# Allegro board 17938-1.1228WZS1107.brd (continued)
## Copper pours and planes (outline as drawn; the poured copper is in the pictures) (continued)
3D3V_S5 on BOTTOM: 54.17,103.89 54.06,104 54.06,106.18 54.31,106.43 54.92,106.43 55.04,106.3 55.04,105.77 55.27,105.54 55.97,105.54 56.22,105.3 56.22,103.91 56.19,103.89
3D3V_S5 on BOTTOM: 146.84,143.84 146.61,144.07 146.61,144.81 146.89,145.09 147.5,145.09 148.01,145.59 148.97,145.59 149.13,145.44 149.13,143.84 ; 2 cut-outs
3D3V_S5 on BOTTOM: 165.43,108.76 165.05,109.15 165.05,109.58 165.18,109.7 165.43,109.7 165.51,109.78 165.51,111.53 165.36,111.69 162.28,111.69 162.23,111.74 162.23,114.66 162.28,114.71 166.58,114.71 167.06,114.23 167.06,108.92 166.91,108.76 ; 1 cut-out
3D3V_S5 on BOTTOM: 34.7,122.28 34.67,122.3 34.67,122.56 34.33,122.9 34.05,122.9 33.91,123.04 33.91,123.34 34.01,123.45 36.12,123.45 36.17,123.39 36.17,123.06 36.02,122.91 35.46,122.91 35.36,122.81 35.36,122.48 35.16,122.28
3D3V_S5 on BOTTOM: 62,119.38 59.64,121.74 59.57,121.74 58.3,123.01 57.58,123.01 56.39,124.21 56.39,125.88 56.29,125.99 56.29,126.39 56.47,126.57 59.41,126.57 59.46,126.62 59.46,127.23 59.49,127.26 60.18,127.26 60.4,127.03 60.4,125.45 60.84,125.02 62.97,125.02 63.58,125.63 63.58,128.07 63.21,128.44 62.47,128.44 62.32,128.59 62.32,128.66 62.28,128.7 60.12,128.7 60.07,128.65 59.52,128.65 59.44,128.73 59.44,129.41 59.01,129.85 59.01,130.58 59.19,130.76 63.76,130.76 64.6,129.92 68.33,129.92 69.04,129.21 69.04,120.27 68.15,119.38 ; 13 cut-outs
3D3V_S5 on L2SGND: 59.95,128.86 58.68,130.13 58.68,134.09 74.27,149.68 97.64,149.68 99.85,147.47 104.8,147.47 107.06,149.73 121.14,149.73 122.99,147.88 126.65,147.88 128.53,149.76 154.21,149.76 154.84,149.12 154.84,147.37 153.47,146 143.59,146 143.21,146.38 141.4,146.38 140.72,145.7 129.67,145.7 128.3,144.32 120.98,144.32 118.88,146.43 108.66,146.43 106.66,144.43 98.28,144.43 97.59,145.11 86.87,145.11 86.11,145.87 77.88,145.87 73.84,141.83 73.31,141.83 71.94,140.46 69.9,140.46 62.06,132.61 62.06,129.49 61.42,128.86
3D3V_S5 on L2SGND: 81.16,28.04 91.85,28.04 92.32,28.51 94,28.51 94.06,28.45 96.73,28.45 97.64,29.36 97.64,32.41 97.03,33.02 95.89,33.02 94.69,31.83 90.73,31.83 90.71,31.8 87.38,31.8 85.83,30.25 81.71,30.25 80.65,31.32 79.1,31.32 78.69,30.91 78.69,30.51
3D3V_S5 on L2SGND: 224.39,64.14 224.39,47.75 224.67,47.47 225.45,47.47 226.01,48.03 226.01,65.94 223.09,68.86 219.66,68.86 219,68.2 218.42,68.2 218.04,67.82 218.04,66.96 218.14,66.85 222.2,66.85 222.76,66.3 222.76,65.76
3D3V_S5 on L2SGND: 50.74,74.23 49.41,72.9 47.63,72.9 47.3,73.23 47.3,73.66 46.97,73.99 46.64,73.99 42.42,69.78 42.09,69.78 41.53,69.22 41.53,68.76 41.79,68.51 42.93,68.51 43.56,69.14 45.39,69.14 45.75,68.78 45.75,68.15 46.08,67.82 46.08,61.49 35.62,51.03 35.62,48 35.23,47.61 35.23,44.26 37.07,42.42 37.9,41.58 51.44,41.58 53.47,39.55 57.71,39.55 57.81,39.65 58.47,39.65 59.52,38.61 62.49,38.61 64.04,37.06 64.47,37.06 65.23,36.3 74.58,36.3 74.91,36.63 75.64,36.63 76.2,36.07 77.5,36.07 77.68,35.89 77.68,37.42 76.08,39.02 66.47,39.02 64.42,41.07 53.55,41.07 51.98,42.64 38.78,42.64 37.6,43.82 37.6,51.54 47.46,61.41 47.46,61.42 47.68,61.63 47.68,66.78 52.29,71.39 52.29,76.8 54.42,78.93 54.42,92.77 54.71,93.07 54.71,93.55 54.46,93.8 53.98,93.8 53.17,92.99 53.17,80.44 50.74,78.01
3D3V_S5 on L3: 161.24,110.78 161.24,112.27 161.88,112.9 161.88,113.77 161.34,114.3 161.34,119.33 160.53,120.14 160.53,130.23 164.82,134.52 164.82,145.72 163.12,147.42 158.19,147.42 157.03,146.25 153.62,146.25 153.37,146.51 153.34,146.51 153.06,146.79 153.06,148.41 155.98,151.33 163.81,151.33 168.2,146.94 168.2,131.01 165.31,128.12 165.31,120.7 164.87,120.27 164.87,112.37 165.79,111.46 165.79,109.09 165.56,108.87 163.11,108.87 157.52,103.28 157.52,97.83 165.79,89.56 165.79,84.56 166.29,84.06 166.29,82.12 177.28,71.13 181.36,71.13 181.89,70.6 181.89,68.71 181.56,68.38 179.25,68.38 178.64,68.99 177.12,68.99 174.43,71.67 174.43,72.07 164.74,81.76 164.74,83.47 164.37,83.84 164.37,88.86 156.16,97.07 156.16,97.2 155.63,97.74 155.63,103.79 157.31,105.46 157.31,105.89 159.01,107.59 159.01,108.55
3D3V_S5 on L4: 220.3,68.43 221.95,68.43 224.25,66.13 224.63,66.13 225.3,65.46 225.3,47.68 224.77,47.14 223.6,47.14 222.94,47.8 222.94,62.89 221.54,64.29 221.54,65.23 220.65,66.12 220.65,66.75 220.42,66.98 219.71,66.98 219.56,67.13 219.56,67.69
3D3V_S5 on L4: 158.98,96.01 159.69,96.01 166.78,88.93 166.78,81.33 177.68,70.44 177.68,69.98 177.42,69.72 177.17,69.72 176.74,70.16 176.74,70.38 165.84,81.28 165.84,88.65 160.51,93.98 160.07,93.98 158.73,95.33 158.73,95.76
3D3V_S5_PCH on TOP: 138.59,91.83 138.16,92.27 137.27,92.27 137.18,92.36 137.18,92.87 137.05,92.99 136.61,92.99 136.47,93.13 136.47,93.3 136.46,93.31 136.46,93.57 136.68,93.8 137.03,93.8 137.17,93.94 137.17,94.8 137.17,94.81 137.17,96.57 137.1,96.63 136.47,96.63 136.39,96.71 136.39,99.3 135.59,100.1 135.59,100.36 135.39,100.56 135.03,100.56 133.51,102.08 133.51,103.97 133.56,104.03 135.27,104.03 136.59,102.71 136.59,101.11 138.1,99.6 138.1,97.23 138.96,96.37 138.96,95.18 139.71,94.43 139.71,92.23 139.32,91.83 ; 4 cut-outs
3D3V_S5_PCH on BOTTOM: 138.92,107.06 138.56,107.42 137.77,107.42 136.83,108.36 135.97,108.36 135.72,108.61 135.72,110.57 136.53,110.57 137.26,109.83 137.26,109.4 137.98,108.69 138.56,108.69 138.64,108.76 140.06,108.76 140.13,108.69 140.13,107.16 140.03,107.06 ; 1 cut-out
3D3V_SSD on TOP: 18.7,21.29 18.39,21.59 18.39,22.94 18.19,23.14 17.22,23.14 17.15,23.22 17.15,26.8 17.3,26.95 20.09,26.95 20.27,26.77 20.27,21.39 20.17,21.29 ; 6 cut-outs
3D3V_SSD on BOTTOM: 18.19,23.6 18.04,23.75 18.02,23.75 18.02,24.42 18.01,24.44 18.01,27.71 20.58,30.28 26.22,30.28 26.25,30.32 34.56,30.32 34.58,30.34 38.44,30.34 38.62,30.51 40.44,30.51 40.82,30.89 41.76,30.89 41.84,30.81 41.84,28.01 41.64,27.81 41.24,27.81 40.71,28.35 38.64,28.35 38.36,28.06 36.65,28.06 36.45,27.87 36.45,24.31 36.2,24.06 32.13,24.06 32.01,24.18 32.01,26.85 31.14,27.71 22.71,27.71 20.2,25.2 20.2,23.67 20.12,23.6 ; 7 cut-outs
3D3V_TPM on TOP: 153.04,141.53 152.4,142.17 152.4,143.05 152.02,143.44 152.02,144.07 152.4,144.45 154.05,144.45 155.32,143.18 155.32,141.91 154.94,141.53 ; 6 cut-outs
3D3V_VCCDSW on BOTTOM: 138.53,80.67 138.48,80.72 138.48,81.26 138.56,81.33 138.92,81.33 139.2,81.61 139.2,81.92 139.75,82.48 139.75,82.73 139.98,82.96 140.61,82.96 140.72,83.07 140.72,85.36 140.88,85.51 141.09,85.51 141.33,85.75 141.33,86.11 141.51,86.29 141.74,86.29 141.96,86.51 141.96,86.82 141.79,87 141.05,87 140.92,87.12 140.92,87.56 141.58,88.22 141.71,88.22 141.81,88.11 142.24,88.11 142.5,88.37 142.5,89.36 142.98,89.84 143.01,89.84 143.61,89.23 143.61,88.42 142.62,87.43 142.62,84.96 142.52,84.86 142.5,84.86 142.12,84.48 142.12,83.39 141,82.27 140.47,82.27 140.41,82.22 140.01,82.22 139.8,82.02 139.8,81.61 139.09,80.9 139.09,80.75 139.02,80.67 ; 1 cut-out
3D3V_VCCPRIM on TOP: 116.36,91.77 116.14,91.99 115.68,91.99 115.62,92.06 115.62,92.52 115.38,92.76 113.49,92.76 113.2,92.47 113.2,92.4 112.97,92.17 112.85,92.17 112.7,92.31 112.7,92.53 113.16,92.99 113.16,93.12 113.22,93.17 113.49,93.17 113.51,93.14 115.09,93.14 115.25,93.31 115.26,93.31 115.48,93.52 117.03,93.52 117.17,93.39 117.17,93.07 117.09,92.99 117.09,92.26 117.25,92.1 117.25,91.82 117.2,91.77 ; 1 cut-out
3D3V_VCCPRIM on BOTTOM: 115.12,92.64 114.86,92.89 114.86,93.52 115.12,93.78 116.77,93.78 117.15,93.4 117.15,92.89 116.89,92.64
3D3V_VCCPRIM on BOTTOM: 130.85,90.39 130.39,90.86 127.16,90.86 126.9,91.11 126.9,91.64 127.23,91.97 127.23,92.25 127.36,92.38 127.69,92.38 127.9,92.17 130.93,92.17 131.15,92.38 135.97,92.38 136.08,92.26 136.08,91.32 132.32,91.32 131.39,90.39 ; 7 cut-outs
3D3V_VCCPRIM on L3: 116.41,97.16 115.56,97.16 115.29,96.89 115.29,96.49 115.23,96.43 115.21,96.43 114.86,96.08 114.86,95.46 115.28,95.04 115.28,94.59 114.41,93.73 111.92,93.73 111.28,94.36 110.65,94.36 110.04,93.75 110.04,93.02 110.29,92.76 112.58,92.76 112.7,92.64 112.7,92.15 113.03,91.82 114.1,91.82 114.99,90.93 120.27,90.93 122.33,88.88 122.71,88.88 122.99,88.6 126.74,88.6 127.25,89.11 131.88,89.11 132.23,89.47 132.23,91.11 132.06,91.29 127.71,91.29 126.93,92.08 123.4,92.08 123.37,92.05 122.91,92.05 121.95,93.02 117.99,93.02 116.82,94.18 116.82,96.75
3D3V_WLAN on TOP: 52.33,98.83 50.01,101.14 47.2,101.14 46.71,101.63 46.13,101.63 45.49,102.26 45.49,103.81 45.51,103.82 45.51,104.36 45.32,104.55 44.66,104.55 44.25,104.95 43.87,104.95 43.82,105 43.82,105.72 44.05,105.94 45.22,105.94 45.29,106.02 45.29,106.58 45.42,106.71 45.85,106.71 46.05,106.5 46.05,106.05 46.13,105.97 47.22,105.97 47.88,106.63 47.88,107.19 48.06,107.37 49.05,107.37 49.28,107.14 49.28,106.25 48.87,105.84 48.44,105.84 48.34,105.74 48.34,105.16 48.52,104.98 51.51,104.98 51.69,104.8 52.12,104.8 52.48,104.45 53.85,104.45 54.23,104.07 54.23,103.05 54.18,103 54.18,102.92 54.11,102.85 53.14,102.85 52.86,102.57 52.86,101.5 53.04,101.32 54.47,101.32 54.7,101.09 54.7,99.21 54.32,98.83 ; 9 cut-outs
3D3V_WLAN on BOTTOM: 51.92,103.71 50.93,104.7 49.53,104.7 49.41,104.57 49.41,104.41 49.32,104.32 48.64,104.32 48.52,104.45 48.52,105.84 48.39,105.97 47.37,105.97 46.87,106.48 46.08,106.48 45.98,106.38 45.98,106.17 45.88,106.07 34.67,106.07 34.27,106.48 32.52,106.48 31.88,105.84 31.88,104.32 29.87,104.32 29.72,104.47 29.72,109.02 30.99,110.29 43.1,110.29 44.89,108.5 47.69,108.5 49.79,106.4 49.84,106.4 50.27,105.97 51.57,105.97 52.54,104.99 53.66,104.99 53.75,104.9 53.75,103.83 53.62,103.71
+DC_IN on TOP: 26.22,123.29 25.99,123.52 25.99,124.16 25.63,124.51 25.63,125.2 25.56,125.27 25.12,125.27 25.02,125.38 25.02,125.71 24.91,125.82 24.37,125.82 24.16,126.04 24.16,128.32 23.95,128.53 23.04,128.53 22.73,128.84 21.06,128.84 20.96,128.93 20.96,130.09 21.1,130.23 26.2,130.23 27.7,131.73 29.35,131.73 29.59,131.48 29.59,129.47 29.47,129.34 28.83,129.34 28.5,129.01 26.41,129.01 26.23,128.83 26.23,128.01 25.61,127.38 25.61,126.7 25.95,126.37 26.37,126.37 26.75,125.99 26.75,125.53 26.32,125.1 26.32,124.56 26.47,124.41 26.85,124.41 27.08,124.18 27.08,123.39 26.98,123.29 ; 5 cut-outs
+DC_IN on L3: 29.09,131.88 27.94,131.88 26.29,130.23 22.86,130.23 22.36,129.72 22.36,128.7 22.74,128.32 27.05,128.32 29.34,130.61 29.34,131.62
+DC_IN on L4: 22.86,130.23 26.29,130.23 27.94,131.88 29.09,131.88 29.34,131.62 29.34,130.61 27.05,128.32 22.74,128.32 22.36,128.7 22.36,129.72
+DC_IN_C on TOP: 21.85,120.59 21.39,121.06 21.39,122.58 20.94,123.04 20.94,124.09 20.16,124.87 20.16,125.51 19.83,125.84 17.47,125.84 17.41,125.89 17.41,127.38 17.43,127.4 19.22,127.4 19.34,127.28 19.95,127.28 20.16,127.48 20.16,129.44 20.22,129.49 20.56,129.49 20.56,129.48 20.62,129.41 20.62,128.5 20.73,128.39 23.76,128.39 23.96,128.2 23.96,125.22 24.29,124.89 24.29,123.19 24.78,122.7 24.78,120.7 24.67,120.59 ; 2 cut-outs
+DC_IN_C on BOTTOM: 21.86,124.14 21.8,124.21 21.8,125.51 20.76,126.55 20.76,127.59 21.2,128.03 24.1,128.03 24.81,127.32 24.81,124.54 24.41,124.14
+SDC_IN on TOP: outline of 94 points within 56.06,57.89 185.09,151.54 ; 2 cut-outs
+SDC_IN on TOP: 34.93,123.5 34.8,123.62 34.8,124.13 34.55,124.39 33.15,124.39 32.57,124.97 31.83,124.97 31.65,125.15 31.12,125.15 30.86,124.89 30.86,124 30.74,123.88 30.34,123.88 29.98,124.24 29.98,124.64 29.85,124.77 29.85,125.88 29.69,126.04 29.09,126.04 28.98,126.14 28.98,126.74 29.06,126.81 29.41,126.81 29.42,126.82 29.42,126.83 29.9,127.31 31.88,127.31 32.03,127.46 32.03,127.89 32.11,127.97 35.03,127.97 35.21,127.79 35.21,126.95 35.18,126.93 34.67,126.93 34.55,126.8 34.55,126.04 34.72,125.86 35.36,125.86 35.82,125.4 35.82,123.75 35.56,123.5 ; 5 cut-outs
+SDC_IN on BOTTOM: 181.61,61.8 183.07,61.8 183.71,61.16 184.53,61.16 184.79,60.91 184.79,58.01 184.77,57.99 182.73,57.99 182.51,58.21 182.51,58.7 181.84,59.36 181.84,59.71 181.38,60.17 181.38,61.57
+SDC_IN on L3: 57.03,138.48 56.65,138.1 56.65,135.28 54.82,133.45 44.05,133.45 43.91,133.31 43.89,133.33 36.91,133.33 32.39,128.8 32.39,126.42 31.83,125.86 31.83,125.22 32.15,124.91 42.23,124.91 44.12,126.8 44.33,126.8 46.99,129.47 52.71,129.47 52.77,129.53 53.91,129.53 59.82,135.43 59.82,137.72 59.06,138.48
+SDC_IN on L4: 36.3,133.02 36.99,133.02 37.39,133.43 55.02,133.43 56.57,134.98 56.59,134.98 56.72,135.1 56.72,138.08 57.13,138.48 61.67,138.48 71.91,148.72 72.6,148.72 73.46,147.85 73.46,146.97 61.83,135.33 59.69,135.33 53.83,129.47 47.12,129.47 44.45,126.8 43.88,126.8 42.1,125.02 33.4,125.02 33.24,125.19 33.07,125.02 32.06,125.02 31.65,125.43 31.65,126.93 32.49,127.76 37.6,127.76 37.75,127.92 37.75,129.01 37.42,129.34 35.89,129.34 35.59,129.64 35.59,132.31
+SDC_IN_SW on TOP: 34.95,126.14 34.9,126.19 34.9,126.7 35,126.8 35.33,126.8 35.39,126.85 35.39,127.61 35.49,127.71 36.22,127.71 36.48,127.46 37.37,127.46 37.8,127.03 37.8,126.19 37.77,126.16 36.45,126.16 36.43,126.19 36.43,126.65 36.27,126.8 35.72,126.8 35.39,126.47 35.39,126.14 ; 1 cut-out
+V_VREF_PATH2 on TOP: 143.68,42.48 143.61,42.55 143.61,42.99 144.08,43.46 144.08,43.76 144.14,43.82 144.56,43.82 144.77,43.61 145.27,43.61 145.38,43.72 145.54,43.72 145.64,43.62 145.64,43.37 145.49,43.22 144.42,43.22 144.07,42.86 144.07,42.57 143.98,42.48
AUD_AGND on TOP: 23.24,8.56 22.58,9.22 21.57,9.22 21.47,9.32 21.47,9.63 21.26,9.83 20.65,9.83 20.45,10.03 20.45,10.62 20.17,10.9 19.56,10.9 18.96,11.49 18.38,11.49 18.21,11.33 18.21,10.85 18.04,10.67 17.58,10.67 17.45,10.8 17.45,12.19 17.05,12.6 17.05,13.06 17.03,13.07 17.03,13.22 16.89,13.36 16.89,15.83 16.94,15.88 17.5,15.88 17.58,15.8 17.58,15.09 18.21,14.45 18.21,12.78 18.98,12.02 20.15,12.02 20.4,11.76 20.4,11.25 20.83,10.82 21.54,10.82 21.72,10.64 21.72,10.03 21.95,9.81 23.27,9.81 23.37,9.7 23.37,9.45 23.6,9.22 23.96,9.22 24.08,9.09 24.08,8.69 23.96,8.56 ; 3 cut-outs
AUD_AGND on TOP: 18.42,18.09 18.42,19.31 18.75,19.64 19.08,19.64 19.69,20.25 20.93,20.25 21.03,20.14 21.03,19.03 20.83,18.82 20.27,18.82 20.12,18.67 19.51,18.67 18.93,18.09 ; 2 cut-outs
AUD_AGND on L2SGND: 22.29,5.2 22.29,6.67 21.82,7.14 14.27,7.14 13.16,8.24 1.41,8.24 1.47,8.39 1.6,8.47 2.3,8.91 2.57,9.7 2.57,10.44 12.71,10.44 13.91,11.3 13.47,12.71 13.47,17.54 13.91,18.95 12.71,19.81 2.57,19.81 2.57,21.27 2.63,21.43 2.77,21.51 3.11,21.62 3.41,21.83 16.23,21.83 17.01,21.06 18.73,21.06 19.48,20.31 20.88,20.31 21.03,20.15 21.03,19.05 21.16,18.92 21.87,18.92 22.22,18.58 22.75,18.58 22.94,18.39 22.94,17.99 24.83,16.1 24.83,12.04 25.2,11.67 27.23,11.67 27.24,11.66 27.24,10.64 28.26,9.63 28.26,8.61 28.39,8.48 28.39,6.32 29.13,5.58 32.48,5.58 33.48,6.58 33.48,9.01 32.34,10.15 31.71,10.15 30.82,11.04 29.67,11.04 29.02,11.69 29.02,12.93 29.04,12.94 29.9,12.94 30.54,12.29 32.31,12.29 32.57,12.55 34.12,12.55 34.17,12.5 34.17,11.86 34.42,11.61 34.8,11.61 34.93,11.48 34.93,5.91 33.83,4.81 23.93,4.81 23.92,4.81 22.69,4.81
AUD_AGND on L5SGND: 13.16,8.24 1.41,8.24 1.47,8.39 1.6,8.47 2.3,8.91 2.57,9.7 2.57,10.44 12.71,10.44 13.91,11.3 13.47,12.71 13.47,17.54 13.91,18.95 12.71,19.81 2.57,19.81 2.57,21.27 2.63,21.43 2.77,21.51 3.11,21.62 3.41,21.83 16.23,21.83 17.01,21.06 18.73,21.06 19.48,20.31 20.88,20.31 21.03,20.15 21.03,19.05 21.16,18.92 21.87,18.92 22.22,18.58 22.75,18.58 22.94,18.39 22.94,17.99 24.83,16.1 24.83,13.48 21.36,10.01 21.36,9.6 18.9,7.14 14.27,7.14
AUD_HP1_JACK_R1 on TOP: 26.95,7.08 26.65,7.37 26.65,7.61 26.79,7.74 26.79,8.29 26.88,8.38 27.3,8.38 27.37,8.31 27.37,7.65 27.55,7.47 27.7,7.47 27.83,7.33 27.83,7.13 27.78,7.08
AUD_RING on TOP: 16.39,10.52 16.34,10.57 16.34,11.13 16.14,11.32 16.14,13.02 16.28,13.16 16.74,13.16 16.87,13.03 16.87,12.47 17.26,12.08 17.26,10.55 17.22,10.52
AUD_RING on TOP: 23.42,14.81 22.71,15.52 22.71,15.98 22.08,16.61 22.08,16.74 22.02,16.79 21.29,16.79 21.26,16.82 21.26,17.27 21.36,17.37 22.13,17.37 23.73,15.77 23.73,15.29 23.88,15.14 23.88,14.96 23.73,14.81
AUD_RING on L3: 22.94,16.33 23.65,16.33 23.9,16.08 23.9,14.05 23.6,13.74 17.86,13.74 17.58,13.46 17.58,11.99 17.15,11.56 16.56,11.56 16.21,11.91 16.21,14.48 16.59,14.86 16.64,14.86 16.77,14.99 22.23,14.99 22.69,15.44 22.69,16.08
AUD_SLEEVE on TOP: 16.74,17.07 16.39,17.43 16.39,18.19 16.54,18.34 17.38,18.34 17.66,18.62 18.16,18.62 18.27,18.52 18.27,17.27 18.06,17.07 ; 1 cut-out
AUD_SLEEVE on TOP: 22.76,14.2 21.97,14.99 21.97,15.14 21.24,15.88 21.24,16.56 21.26,16.59 21.87,16.59 22.56,15.9 22.56,15.5 23.37,14.68 23.52,14.68 23.65,14.56 23.65,14.28 23.57,14.2
AUD_SPK_L+ on TOP: 17.33,4.93 17.15,5.11 17.15,5.79 17.25,5.89 20.81,5.89 21.06,5.64 21.06,5.16 20.83,4.93 19.84,4.93 19.79,4.98 18.37,4.98 18.32,4.93 ; 2 cut-outs
AUD_SPK_L+ on TOP: 30.58,12.98 30.18,13.39 30.18,13.44 30.33,13.59 30.36,13.59 30.53,13.41 30.84,13.41 31.22,13.79 31.58,13.79 31.78,13.59 31.78,13.18 31.58,12.98
AUD_SPK_L+ on BOTTOM: 29.92,11.79 29.58,12.13 29.58,12.6 29.9,12.93 30.51,12.93 31.22,13.64 31.5,13.64 31.75,13.39 31.75,12.65 30.9,11.79
AUD_SPK_L+_C on TOP: 15.5,5.06 15.32,5.23 15.32,6.3 15.47,6.45 16.44,6.45 16.94,5.94 16.94,5.16 16.84,5.06
AUD_SPK_L+_C on BOTTOM: 8.94,4.83 8.78,4.99 8.78,7.27 8.87,7.36 9.46,7.36 9.57,7.25 9.57,4.89 9.5,4.83
AUD_SPK_L- on TOP: 18.23,3.54 18.14,3.63 17.3,3.63 17.12,3.81 17.12,4.5 17.22,4.6 17.99,4.6 18.32,4.27 19.71,4.27 19.88,4.1 20.27,4.1 20.41,3.96 20.41,3.7 20.25,3.54
AUD_SPK_L- on BOTTOM: 29.27,13.15 28.78,13.64 28.78,13.76 29.43,14.4 30.89,14.4 31.09,14.2 31.09,13.79 30.76,13.46 30.75,13.46 30.44,13.15
AUD_SPK_L-_C on TOP: 14.3,3.89 14.07,4.12 14.07,4.8 14.2,4.93 16.82,4.93 16.94,4.8 16.94,3.96 16.87,3.89
AUD_SPK_L-_C on BOTTOM: 7.64,4.89 7.39,5.13 7.39,7.25 7.53,7.39 8.42,7.39 8.51,7.29 8.51,4.98 8.42,4.89
AUD_SPK_R+ on TOP: 18.37,1.2 18.21,1.35 17.43,1.35 17.15,1.63 17.15,2.21 17.25,2.31 17.91,2.31 18.04,2.19 18.06,2.19 18.19,2.06 18.29,2.06 18.44,1.91 19,1.91 19.15,2.06 20.06,2.06 20.31,1.8 20.31,1.46 20.2,1.35 19.1,1.35 18.95,1.2
AUD_SPK_R+ on BOTTOM: 33.28,13.87 33.28,14 31.91,15.37 31.07,15.37 30.91,15.22 30.91,14.81 30.71,14.61 30.1,14.61 29.87,14.83 29.87,15.93 30.43,16.49 32.39,16.49 34.27,14.61 34.27,14.05 34.09,13.87
AUD_SPK_R+_C on TOP: 15.6,1.37 15.4,1.58 15.4,2.29 15.52,2.41 16.82,2.41 16.97,2.26 16.97,1.6 16.74,1.37
AUD_SPK_R+_C on BOTTOM: 11,2.77 10.87,2.9 10.87,6.48 10.93,6.53 11.61,6.53 11.79,6.35 11.79,3.07 11.48,2.77
AUD_SPK_R- on TOP: 30.38,14.4 30.31,14.48 30.31,14.61 30.36,14.66 30.69,14.66 30.89,14.86 30.89,15.22 31.09,15.42 31.47,15.42 31.63,15.27 31.63,14.66 31.37,14.4
AUD_SPK_R- on TOP: 17.22,2.59 17.07,2.74 17.07,3.4 17.12,3.46 20.75,3.46 20.88,3.33 20.88,2.9 20.73,2.74 19.89,2.74 19.84,2.8 18.37,2.8 18.32,2.74 18.06,2.74 17.91,2.59
AUD_SPK_R- on BOTTOM: 32.34,13.29 31.04,14.58 31.04,15.11 31.22,15.29 31.78,15.29 33.02,14.05 33.02,13.46 32.85,13.29
AUD_SPK_R-_C on TOP: 15.52,2.67 15.42,2.77 15.42,3.58 15.52,3.68 16.82,3.68 16.94,3.56 16.94,2.77 16.84,2.67
AUD_SPK_R-_C on BOTTOM: 9.97,3.91 9.87,4.01 9.87,6.47 9.93,6.53 10.54,6.53 10.59,6.48 10.59,4.17 10.34,3.91
BT+ on TOP: 142.64,30.62 142.55,30.71 142.55,32.16 142.65,32.26 148.87,32.26 149.43,32.82 149.43,33.43 149.84,33.83 153.85,33.83 153.9,33.78 153.9,32.39 154.03,32.26 172.72,32.26 172.93,32.46 173.51,32.46 173.84,32.13 173.84,30.9 173.56,30.62 ; 3 cut-outs
BT+ on BOTTOM: 142.69,31.06 142.37,31.37 142.37,40.97 142.47,41.07 144.88,41.07 145.93,40.03 148.62,40.03 148.85,39.8 152.02,39.8 152.75,39.08 152.75,34.56 153.6,33.71 169.68,33.71 169.85,33.88 177.55,33.88 177.75,33.68 177.75,33.31 177.84,33.23 179.33,33.23 179.33,33.22 179.64,33.22 179.91,32.95 179.91,32.16 179.58,31.82 177.77,31.82 177.61,31.66 177.61,31.35 177.31,31.06 ; 7 cut-outs
DCBATOUT on TOP: 77.85,28.25 77.73,28.37 77.73,29.69 78.01,29.97 79.81,29.97 80.9,28.88 81.41,28.88 81.66,28.63 81.66,28.37 81.54,28.25 ; 1 cut-out
DCBATOUT on TOP: 170.89,57.2 163.27,64.82 163.27,67.29 161.84,68.72 161.05,68.72 152.89,76.88 152.1,76.88 151.18,77.8 151.18,85.6 150.17,86.62 150.17,89.84 147.42,92.58 145.29,92.58 140.25,97.63 140.25,100.06 136.52,103.8 136.52,116.45 136.12,116.84 136.12,124 137.21,125.1 137.21,128.47 135.09,130.6 135.09,131.92 135.26,132.08 136.07,132.08 138.05,130.1 138.56,130.1 139.09,129.57 139.09,126.65 139.47,126.26 144.07,126.26 144.08,126.25 146.12,126.25 146.26,126.39 152.56,126.39 153.76,127.6 162.95,127.6 163.53,127.02 163.53,123.29 162.63,122.39 162.22,122.39 161.24,121.41 144.28,121.41 143.69,120.83 143.69,112.07 145.72,110.03 145.74,110.03 145.74,107.53 154.28,98.99 154.28,95.71 161.01,88.98 161.01,80.82 171.41,70.42 171.41,66.31 175,62.73 175,60.7 174.98,60.69 174.98,59.26 172.93,57.2 ; 15 cut-outs
DCBATOUT on TOP: 131.36,32.3 129.97,33.7 129.05,33.7 128.2,34.54 126.13,34.54 126.06,34.47 118.81,34.47 118.46,34.82 118.46,35.63 118.3,35.79 118.3,38.09 119.14,38.93 120.64,38.93 121.75,40.03 122.53,40.03 124.08,41.58 146.62,41.58 146.85,41.8 151.13,41.8 151.86,42.53 151.86,42.53 152.04,42.71 163.33,42.71 163.79,43.17 172.43,43.17 173.71,44.45 175.63,44.45 175.89,44.71 175.89,49.82 174.34,51.36 174.34,52.78 175.4,53.83 176.6,53.83 176.82,54.05 179.76,54.05 184.53,49.28 184.53,42.79 184.13,42.38 184.13,40.44 184.13,40.44 184.13,40.06 184.69,39.5 185.07,39.5 185.32,39.24 185.32,37.11 182.42,34.2 178.77,34.2 178.23,34.74 178.23,36.42 177.57,37.09 173.87,37.09 171.36,39.59 166.58,39.59 165.71,40.45 162.36,40.45 162.36,40.46 161.42,40.46 161.24,40.64 159.69,40.64 159.51,40.45 155.98,40.45 154,38.48 153.68,38.48 148.9,33.7 148.9,33.38 148.19,32.67 138.08,32.67 137.71,32.3 ; 23 cut-outs
DCBATOUT on TOP: 85.47,28.5 85.22,28.75 85.22,29.01 86.24,30.02 89.92,30.02 90.68,30.79 91.82,30.79 92.08,30.53 92.08,29.9 90.68,28.5 ; 4 cut-outs
DCBATOUT on BOTTOM: 166.18,39.76 165.28,40.67 155.12,40.67 154.84,40.39 153.17,40.39 152.59,40.97 152.59,41.55 152.88,41.84 168.07,41.84 168.56,41.35 168.56,40.15 168.18,39.76
DCBATOUT on BOTTOM: 182.87,31.18 182.3,31.75 180.48,31.75 180.08,32.15 180.08,32.99 179.73,33.33 178.51,33.33 178.23,33.61 178.23,35.3 178.54,35.61 178.54,36.35 178.67,36.48 180.62,36.48 180.98,36.12 182.69,36.12 182.86,36.29 182.86,38.98 182.26,39.59 182.03,39.59 182.02,39.6 181.28,39.6 181.23,39.65 181.23,42.14 181.38,42.29 184.48,42.29 184.59,42.19 184.59,39.81 185.32,39.09 185.32,36.8 184.15,35.63 184.15,34.64 183.85,34.34 183.85,31.28 183.75,31.18 ; 10 cut-outs
DCBATOUT on BOTTOM: 176.07,51.87 175.52,52.41 175.52,53.93 175.53,53.93 175.53,54.58 176.86,55.92 176.86,57.58 175.72,58.73 175.72,61.34 175.59,61.47 171.96,61.47 171.15,62.28 171.15,64.39 171.16,64.4 171.16,65.06 171.4,65.3 173.26,65.3 173.92,64.64 178.59,64.64 179.17,65.23 179.17,65.79 179.38,65.99 180.85,65.99 180.98,65.86 180.98,65 180.8,64.82 180.58,64.82 180.19,64.44 180.19,60 180.2,59.99 180.2,58.85 180.36,58.7 180.59,58.7 180.77,58.52 180.77,57.25 181.01,57.01 182.33,57.01 183.14,57.81 185.98,57.81 186.05,57.74 186.05,53.56 185.43,52.94 180.2,52.94 179.12,51.87
DCBATOUT on BOTTOM: 122.94,148.24 125.17,148.18 126.52,148.26 130.08,151.69 165.81,151.69 167.74,149.76 167.74,123.14 167.47,122.86 162.61,122.86 162.49,122.99 162.49,127.18 163.48,128.17 163.48,128.6 163.59,128.72 163.59,138.52 163.6,138.53 163.6,140.49 163.66,140.54 163.66,142.6 163.66,142.6 163.66,145.98 162.3,147.33 154.12,147.33 154.1,147.35 130.41,147.35 127.47,144.41 120.89,144.41 119.92,145.39 108.23,145.39 108.04,145.2 108.04,144.77 107.9,144.63 107.8,144.63 107.6,144.43 99.16,144.43 98.69,144.9 95.14,144.9 93.66,146.38 85.42,146.38 85.25,146.2 85.25,145.85 84.99,145.59 77.09,145.59 75.26,143.77 74.02,143.77 71.66,141.4 71.66,140.31 71.71,140.26 71.71,139.83 71.66,139.78 71.12,139.78 71.05,139.85 71.05,140.82 70.87,141 68.53,141 68,140.46 67.57,140.46 67.45,140.35 67.45,138.92 67.21,138.69 67.21,137.21 67.67,136.75 67.67,135.56 67.59,135.48 66.42,135.48 66.17,135.74 64.19,135.74 63.99,135.94 63.99,141.05 64.1,141.16 66.99,142.51 68.34,145.4 74.22,151.28 97.39,151.28 100.29,148.38 103.37,148.38 106.1,151.11 120.09,151.11 ; 79 cut-outs
DCBATOUT on BOTTOM: 77.85,27.74 77.73,27.87 52.07,27.87 52.07,27.89 51.4,28.56 50.94,28.56 50.78,28.73 50.37,28.73 50.02,29.08 45.5,29.08 43.8,30.78 43.79,30.78 42.54,32.03 41.43,32.03 41.41,32.01 39.68,32.01 39.09,32.59 39.09,33.05 38.66,33.48 38.66,33.86 38.69,33.88 39.73,33.88 40.01,34.16 40.01,34.85 40.52,35.36 41.66,35.36 41.79,35.23 41.79,34.34 42.06,34.07 43.94,34.07 43.94,34.06 49.3,34.06 49.33,34.04 50.88,34.04 51.11,33.81 51.11,32.46 52.23,31.34 75.31,31.34 75.35,31.38 75.44,31.29 81.11,31.29 81.7,30.7 91.71,30.7 91.72,30.68 91.9,30.68 92.36,31.14 94.72,31.14 94.8,31.07 94.8,30.63 94.72,30.56 93.17,30.56 92.21,29.59 92.21,28.12 91.82,27.74 ; 4 cut-outs
DCBATOUT on L3: 122.58,32.95 127,32.95 127.51,33.45 127.51,35.23 126.88,35.87 124.08,35.87 121.77,38.18 120.91,38.18 119.34,39.75 113.24,39.75 107.72,34.24 107.72,33.1 106.25,31.62 101.15,31.62 100.33,32.44 97.67,32.44 97.03,31.8 95.63,31.8 94.86,32.58 91.43,32.58 89.69,30.84 81.41,30.84 80.6,30.02 77.9,30.02 77.6,29.72 77.6,28.25 78.11,27.74 91.19,27.74 91.95,28.5 92.59,28.5 93.35,27.74 107.95,27.74 110.62,30.41 110.62,33.07 110.77,33.22 110.77,34.14 113.87,37.24 118.29,37.24
DCBATOUT on L4: 126.62,35.87 123.96,35.87 121.67,38.15 120.91,38.15 119.38,39.68 113.16,39.68 107.7,34.22 107.7,33.07 106.18,31.55 105.03,31.55 104.78,31.29 104.78,30.66 105.03,30.41 109.1,30.41 110.62,31.93 110.62,33.99 113.86,37.22 118.28,37.22 121.92,33.58 126.5,33.58 127.13,34.22 127.13,35.36
DCBATOUT_LCD on BOTTOM: 215.01,36.88 214.91,36.98 214.91,37.77 214.94,37.8 215.67,37.8 215.95,38.07 215.95,40.04 215.65,40.34 215.01,40.34 214.86,40.49 214.86,42.42 214.94,42.5 215.75,42.5 216.13,42.11 216.13,41.5 216.54,41.1 217.12,41.1 217.5,40.72 217.5,40.26 217.08,39.84 217.08,39.51 218.21,38.38 218.21,38.33 218.34,38.2 219.41,38.2 219.46,38.15 219.46,37.49 219.36,37.39 218.6,37.39 218.16,36.96 217.66,36.96 217.22,37.39 216.97,37.39 216.46,36.88 ; 2 cut-outs
DCBATOUT_LCD_R on BOTTOM: 214.81,38.23 214.07,38.96 213.08,38.96 212.98,39.07 212.98,42.39 213.06,42.47 214.68,42.47 214.71,42.44 214.71,40.36 214.89,40.18 215.67,40.18 215.85,40.01 215.85,38.33 215.75,38.23 ; 1 cut-out
HDMI_PLL_GND on L3: 24.28,102.29 24.06,102.29 23.85,102.08 23.85,101.78 25.67,99.95 25.67,99.85 23.69,97.86 23.69,96.38 23.12,95.82 23.12,92.87 23.28,92.71 23.67,92.71 23.78,92.82 23.78,95.47 24.39,96.09 24.39,97.63 26.46,99.69 26.46,100.11
JGND on TOP: 17.06,124.61 16.99,124.69 16.99,124.87 15.98,125.87 15.5,125.87 15.18,126.19 15.18,126.94 15.41,127.16 15.6,127.16 15.76,127.32 15.76,128.28 15.76,128.29 15.76,128.8 15.82,128.87 19.18,128.87 19.18,129.59 19.31,129.72 19.77,129.72 19.88,129.61 19.88,127.53 19.77,127.42 19.43,127.42 19.3,127.55 17.26,127.55 17.18,127.47 17.18,125.87 17.45,125.6 17.45,124.73 17.33,124.61 ; 1 cut-out
JGND on BOTTOM: 17.07,124 16.85,124.22 16.85,124.48 15.18,126.15 15.18,126.95 15.27,127.04 18.34,127.04 19.56,125.82 19.56,124.26 19.31,124
M_VREF_CA_DIMMA on TOP: 71.48,41.2 71.33,41.35 71.33,42.44 71.55,42.67 71.99,42.67 72.19,42.88 72.19,42.98 72.22,43 72.22,43.92 72.62,44.32 72.62,44.6 72.82,44.81 73.16,44.81 73.36,44.6 73.36,42.47 72.77,41.89 72.77,41.35 72.62,41.2 ; 1 cut-out
M_VREF_CA_DIMMB on TOP: 145.98,42.47 145.9,42.55 145.9,43.16 146,43.26 146.41,43.26 146.71,43.56 148.09,43.56 149.15,44.63 149.33,44.63 149.41,44.55 149.41,44.5 149.51,44.4 149.51,44.3 149.15,43.94 149.15,42.7 148.92,42.47 ; 2 cut-outs
MCT on TOP: 25.08,85.26 24.87,85.47 24.87,86.52 25.02,86.67 27.08,86.67 27.08,86.67 27.23,86.67 27.26,86.64 27.26,85.4 27.12,85.26
MCT on BOTTOM: 26.29,82.78 25,84.07 25,86.17 25.3,86.46 26.27,86.46 27.49,85.24 27.49,82.98 27.28,82.78
PWR_1D05V_PH on BOTTOM: 114.94,134.16 114.62,134.49 114.62,137.02 114.33,137.31 114.33,138.09 114.39,138.15 115.01,138.15 115.33,138.48 116.18,138.48 116.39,138.69 117.15,138.69 117.25,138.79 117.25,139.29 117.27,139.32 120.88,139.32 120.91,139.29 120.91,138.39 120.88,138.36 120.32,138.36 120.22,138.46 118.21,138.46 118.06,138.3 118.06,137.31 118.09,137.29 120.32,137.29 120.42,137.19 120.42,134.29 120.3,134.16 ; 1 cut-out
PWR_1D8V on TOP: 81.56,28.86 80.5,29.92 80.5,37.09 78.34,39.24 76.48,39.24 75.59,38.36 68.18,38.36 67.69,38.84 67.69,41.12 67.82,41.25 68.94,41.25 70.59,39.6 75.14,39.6 76.03,40.49 79.3,40.49 81.79,38 81.79,30.66 82.2,30.25 83.44,30.25 85.02,31.83 88.83,31.83 91.7,34.7 91.7,36.45 91.57,36.58 91.57,38.15 91.29,38.43 91.29,39.12 91.6,39.42 92.46,39.42 92.81,39.07 93.58,39.07 93.78,38.86 93.78,34.49 89.51,30.23 86.01,30.23 84.64,28.86 ; 2 cut-outs
PWR_1D8V on BOTTOM: 91.42,37.04 91.19,37.28 91.19,38.88 91.2,38.88 91.72,39.39 91.72,40.49 92.05,40.82 92.77,40.82 92.91,40.69 92.91,39.85 93.67,39.09 93.67,37.12 93.6,37.04 ; 1 cut-out
PWR_1D8V_FB_A on TOP: 90.71,37.33 90.6,37.45 90,37.45 89.93,37.52 89.93,38.06 90.84,38.98 91.02,38.98 91.14,38.85 91.14,38.24 91.29,38.09 91.29,37.41 91.21,37.33 ; 1 cut-out
PWR_1D8V_VIN on BOTTOM: 94.15,33.57 93.93,33.78 93.93,39.17 94.36,39.6 99.88,39.6 99.95,39.52 99.95,38.86 99.85,38.76 99.11,38.76 98.63,38.28 97.13,38.28 96.95,38.1 96.95,34.7 96.62,34.37 96.62,33.71 96.48,33.57
PWR_2D5V on BOTTOM: 164.37,114.94 164.32,114.99 164.32,119.77 164.94,120.4 165.55,120.4 166.04,119.9 166.26,119.9 166.58,119.58 166.58,115.16 166.35,114.94 ; 6 cut-outs
PWR_3D3V_FB2 on BOTTOM: 72.31,134.69 72.21,134.79 72.21,135.99 72.74,136.52 73.29,136.52 73.43,136.38 73.43,136.15 72.93,135.64 72.93,134.9 72.72,134.69 ; 1 cut-out
PWR_3D3V_LDO on BOTTOM: 70.59,132.46 70.44,132.61 70.44,133.66 70.06,134.04 68.99,134.04 68.79,134.24 68.79,135.23 68.81,135.26 69.14,135.26 69.51,134.89 70.31,134.89 70.78,134.42 72.91,134.42 72.96,134.37 72.96,133.81 72.77,133.63 72.17,133.63 71.96,133.41 71.96,132.7 71.76,132.5 71.54,132.5 71.5,132.46 ; 1 cut-out
PWR_3D3V_PH on BOTTOM: 65.26,131.14 65.13,131.27 65.13,134.67 65.26,134.8 67.34,134.8 67.77,135.23 68.13,135.23 68.13,134.09 68.28,133.94 68.71,133.94 68.86,133.78 68.86,131.29 68.71,131.14 ; 1 cut-out
PWR_5V_PH on BOTTOM: 42.42,34.98 41.91,35.49 41.91,35.61 42.04,35.74 43.06,35.74 43.18,35.87 43.18,39.3 43.44,39.55 45.98,39.55 46.1,39.43 46.1,35.5 45.57,34.98
PWR_5V_VCC on BOTTOM: 42.04,36.37 41.91,36.5 41.91,36.76 42.42,37.26 42.42,38.03 42.29,38.15 42.29,38.41 42.04,38.66 42.04,39.8 42.17,39.93 43.06,39.93 43.06,36.5 42.93,36.37
PWR_CHG_ASGATE22 on TOP: 198.2,51.74 197.92,52.02 197.92,52.91 198.15,53.14 199.06,53.14 199.16,53.04 199.16,52.38 199.37,52.17 199.37,51.87 199.24,51.74 ; 1 cut-out
PWR_CHG_HG1_R on BOTTOM: 191.62,51.46 191.27,51.82 191.27,52.25 191.52,52.5 192.43,52.5 192.59,52.35 192.59,51.61 192.43,51.46
PWR_CHG_HG2_R on TOP: 195.02,49.25 194.77,49.51 194.77,50.06 194.97,50.27 197.13,50.27 197.21,50.19 197.21,49.38 197.08,49.25
PWR_CHG_HG2_R on BOTTOM: 183.8,42.55 183.72,42.62 183.72,43.36 184.94,43.36 185.19,43.61 185.19,44.5 185.37,44.68 185.75,44.68 185.96,44.48 185.96,43.13 185.37,42.55
PWR_CHG_LGATE1 on TOP: 191.65,47.7 191.44,47.91 191.44,48.21 191.82,48.59 192.48,48.59 192.64,48.44 192.64,48.24 192.1,47.7
PWR_CHG_LGATE1 on BOTTOM: 201.2,50.7 200.76,51.13 200.76,51.51 200.97,51.72 201.53,51.72 201.93,51.31 201.93,50.73 201.91,50.7
PWR_CHG_LGATE1 on BOTTOM: 191.6,47.56 191.43,47.73 191.43,48.26 191.63,48.46 192.58,48.46 192.69,48.35 192.69,47.59 192.66,47.56
PWR_CHG_LGATE1 on L4: 198.83,51.89 201.32,51.89 201.65,51.56 201.65,51.16 201.37,50.88 199.24,50.88 196.7,48.34 194.06,48.34 193.32,47.6 191.44,47.6 191.32,47.73 191.32,48.49 191.52,48.69 192.89,48.69 193.55,49.35 196.29,49.35
PWR_CHG_LGATE2 on TOP: 195.13,50.47 194.87,50.73 194.87,51.18 195.02,51.33 196.12,51.33 196.29,51.51 197.13,51.51 197.21,51.44 197.21,50.62 197.06,50.47
PWR_CHG_LGATE2 on BOTTOM: 180.01,42.65 179.99,42.67 179.99,43.61 180.5,44.12 181.13,44.12 181.31,43.94 181.31,43.61 180.5,42.8 180.5,42.77 180.37,42.65
PWR_CHG_LGATE2/ASGATE on TOP: 198.83,50.09 198.45,50.47 197.79,50.47 197.67,50.6 197.67,51.44 197.79,51.56 199.27,51.56 199.34,51.49 199.34,50.98 199.44,50.88 199.8,50.88 200.03,50.65 200.03,50.29 199.82,50.09 ; 1 cut-out
PWR_CHG_PHASE1 on TOP: 189.62,51.03 189.58,51.07 189.02,51.07 188.85,51.23 188.85,51.69 189.04,51.88 191.1,51.88 191.17,51.8 191.17,51.1 191.1,51.03
PWR_CHG_PHASE1 on BOTTOM: 186.52,46.79 186.31,46.99 186.31,50.78 187.4,51.87 191.01,51.87 191.54,51.33 192.66,51.33 192.81,51.49 192.81,52.27 193.04,52.5 195.23,52.5 195.46,52.27 195.46,51.87 195.2,51.61 195.2,48.69 195.08,48.57 191.48,48.57 191.29,48.38 191.29,46.97 191.11,46.79
PWR_CHG_PHASE1 on L4: 195.94,51.87 198.38,51.87 198.72,52.21 200.91,52.21 201.03,52.33 201.03,52.75 200.62,53.16 198.2,53.16 197.92,52.88 194.95,52.88 194.62,52.55 194.62,52.07 194.92,51.77 195.25,51.77 195.46,51.97 195.84,51.97
PWR_CHG_PHASE2 on BOTTOM: 196.35,47.58 196.09,47.83 196.09,50.57 196.48,50.96 197.7,50.96 197.77,50.9 197.77,50.01 197.67,49.92 196.92,49.92 196.83,49.83 196.83,47.78 196.62,47.58
PWR_CHG_PHASE2 on BOTTOM: 177.63,39.55 177.42,39.75 177.42,39.77 177.38,39.8 173.99,39.8 173.9,39.89 173.9,42.25 174.88,43.23 174.88,48.11 177.92,51.15 183.45,51.15 185.2,49.39 185.2,44.83 184.97,44.59 184.97,43.69 184.79,43.51 183.62,43.51 183.52,43.41 183.52,42.72 183.34,42.55 181.23,42.55 180.98,42.29 180.98,39.68 180.85,39.55 ; 1 cut-out
PWR_CHG_SNB on TOP: 190,48.46 189.66,48.79 189.66,50.29 189.87,50.5 191.09,50.5 191.14,50.45 191.14,48.59 191.01,48.46 ; 2 cut-outs
PWR_CHG_UGATE1 on L4: 197.11,54.76 200.63,54.76 202.68,52.71 202.68,52.06 202.51,51.89 201.86,51.89 201.65,52.1 201.65,52.42 200.36,53.72 197.69,53.72 197.51,53.54 196.88,53.54 196.61,53.81 196.61,54.27
PWR_CHG_UGATE2 on TOP: 199.6,48.41 199.14,48.87 197.95,48.87 197.67,49.15 197.67,50.17 197.77,50.27 198.45,50.27 198.85,49.87 199.44,49.87 199.98,49.33 200.41,49.33 200.56,49.18 200.56,48.77 200.21,48.41 ; 2 cut-outs
PWR_CHG_VBATIN on BOTTOM: 170.39,34.24 170.03,34.6 170.03,37.06 169.87,37.22 169.15,37.22 168.91,37.47 168.91,38.18 168.62,38.47 168.62,39.66 169.4,40.44 171.86,40.44 172.04,40.26 172.04,36.36 172.12,36.27 175.44,36.27 175.87,35.84 175.87,35.51 176.23,35.15 176.23,34.34 176.13,34.24
PWR_CHG_VBATIN_R on BOTTOM: 176.18,35.38 176,35.56 176,36.06 175.66,36.4 172.24,36.4 172.22,36.43 172.22,40.32 172.3,40.41 173.41,40.41 173.69,40.13 173.69,39.6 173.89,39.4 182.25,39.4 182.43,39.22 182.43,36.24 182.43,36.24 181.12,36.24 180.77,36.58 177.57,36.58 177.46,36.46 176.98,36.46 176.53,36.02 176.53,35.46 176.46,35.38
PWR_DCBATOUT_1D05V on BOTTOM: 121.25,138.84 121.16,138.93 121.16,139.73 121.07,139.83 117.33,139.83 117.27,139.88 117.27,141.1 117.3,141.12 120.22,141.12 121.08,141.99 121.08,144.07 121.14,144.12 123.99,144.12 124.08,144.03 124.08,143.67 124.01,143.6 123.5,143.6 123.4,143.5 123.4,140.1 123.56,139.94 124.33,139.94 124.38,139.89 124.38,138.91 124.31,138.84 ; 3 cut-outs
PWR_DCBATOUT_VCCGTA on TOP: 90.57,138.19 90.27,138.48 90.27,140.94 90.51,141.17 99.11,141.17 99.49,141.56 99.49,142.62 99.69,142.81 99.69,142.83 99.85,142.99 99.85,143.66 100.1,143.92 101.32,143.92 101.6,143.64 101.6,139.37 101.02,138.79 96.61,138.79 96.02,138.19 ; 5 cut-outs
PWR_DCBATOUT_VCCGTA on BOTTOM: 91.34,138 91.28,138.06 91.28,138.27 91.27,138.28 91.27,138.84 91.11,138.99 88.4,138.99 88.37,139.02 88.37,140.08 88.45,140.16 89.79,140.16 89.94,140.31 89.94,141.12 90,141.17 92.69,141.17 92.99,140.87 92.99,139.63 93.53,139.09 93.53,138.23 93.3,138 ; 1 cut-out
PWR_DCBATOUT_VCCGTA on BOTTOM: 97.16,139.02 97.06,139.12 97.06,140.16 97.11,140.21 98.48,140.21 98.66,140.39 98.66,141.35 98.78,141.48 99.27,141.48 99.42,141.63 99.42,142.52 99.37,142.57 99.37,144.02 99.42,144.07 104.17,144.07 104.35,143.89 104.35,139.37 103.99,139.02 ; 7 cut-outs
PWR_DCBATOUT_VCCGTA on L3: 90.43,141.28 99.06,141.28 99.57,141.78 99.57,142.55 99.7,142.67 101.22,142.67 101.6,142.29 101.6,139.63 100.84,138.86 90.55,138.86 90.17,139.24 90.17,141.02
PWR_DCBATOUT_VCCSA on BOTTOM: 104.98,136.93 104.94,136.97 104.94,141.34 105.64,142.04 105.64,142.67 105.18,143.13 105.18,144.02 105.31,144.15 107.55,144.15 107.72,144.32 107.95,144.32 108.08,144.2 108.08,143.13 107.93,142.98 107.93,139.83 108.44,139.32 108.44,136.96 108.41,136.93 ; 3 cut-outs
PWR_DCBATOUT_VCORE on TOP: 81.71,140.29 79.71,142.29 79.71,143.31 79.96,143.56 79.96,144.6 80.14,144.78 83.41,144.78 84.33,143.86 84.33,140.62 84,140.29 ; 4 cut-outs
PWR_DCBATOUT_VCORE on BOTTOM: 77.8,138.89 77.75,138.94 77.75,140.06 77.78,140.08 79.23,140.08 79.28,140.13 79.28,142.9 79.28,142.91 79.28,144.4 79.56,144.68 80.82,144.68 81.23,145.09 84.2,145.09 84.84,144.45 84.84,144.2 84.94,144.1 85.19,144.1 85.27,144.02 85.27,143.36 84.84,142.93 84.84,140.13 83.59,138.89 ; 11 cut-outs
PWR_DCBATOUT_VDDQ on TOP: 116.7,30.49 116.56,30.63 116.56,33.05 117.19,33.68 117.22,33.68 117.65,34.1 118.48,34.1 118.6,34.22 121.54,34.22 121.77,33.98 121.77,32.34 121.42,31.98 118.88,31.98 118.72,31.83 117.91,31.83 117.71,31.62 117.71,31.14 117.06,30.49 ; 6 cut-outs
PWR_DCBATOUT_VDDQ on BOTTOM: 116.21,29.92 116.16,29.97 116.16,31.57 116,31.73 116,32.39 116.26,32.64 118.82,32.64 119.51,33.33 119.51,35.13 119.81,35.43 122.99,35.43 123.17,35.26 123.17,33.4 121.39,31.62 118.93,31.62 118.88,31.68 117.48,31.68 117.38,31.57 117.38,30 117.3,29.92
PWR_VCCGT_SWA on TOP: 93.75,131.09 92.94,131.91 92.94,133.63 93.22,133.91 94.62,133.91 94.87,133.66 94.87,131.75 94.21,131.09
PWR_VCCGT_SWA on BOTTOM: 93.74,132.6 93.17,133.17 93.17,135.54 93.75,136.12 93.75,137.31 94.29,137.85 94.95,137.85 94.97,137.82 94.97,136.53 95.15,136.35 98.94,136.35 98.96,136.32 98.96,133.36 98.2,132.6
PWR_VCCGT_SWB on BOTTOM: 86.24,132.51 85.55,133.2 85.55,137.75 85.6,137.8 86.24,137.8 86.39,137.64 86.39,136.42 86.49,136.32 90.68,136.32 90.95,136.06 90.95,132.69 90.77,132.51
PWR_VCCSA_DRVH on BOTTOM: 104.7,135.56 104.63,135.64 104.63,136.25 104.73,136.35 105.9,136.35 105.92,136.32 105.92,135.64 105.84,135.56
PWR_VCCSA_DRVH on BOTTOM: 110.19,142.6 110.04,142.75 110.04,143.49 110.24,143.69 111.33,143.69 111.38,143.64 111.38,143.08 111.36,143.05 111,143.05 110.9,142.95 110.9,142.77 110.72,142.6
PWR_VCCSA_DRVL on BOTTOM: 111.23,138.66 111.18,138.71 111.18,139.4 111.23,139.45 112.22,139.45 112.64,139.87 112.64,141.01 112.58,141.07 112.58,141.63 112.6,141.66 113.19,141.66 113.33,141.52 113.33,139.33 112.65,138.66
PWR_VCCSA_SW on BOTTOM: 106.38,132.72 105.69,133.4 105.69,134.98 106.15,135.43 106.15,136.35 106.18,136.37 108.41,136.37 108.64,136.6 108.64,138.02 108.82,138.2 111.92,138.2 112.08,138.04 112.08,134.2 110.59,132.72
PWR_VCCSA_SW on BOTTOM: 110.76,141.01 110.52,141.25 110.16,141.25 109.93,141.48 109.93,142.01 110.06,142.14 110.65,142.14 111.13,141.66 111.38,141.66 111.41,141.63 111.41,141.1 111.32,141.01
PWR_VCORE_SW on BOTTOM: 75.64,132.31 74.07,133.88 74.07,137.47 74.32,137.72 75.57,137.72 75.59,137.69 75.59,136.37 75.75,136.22 79.63,136.22 80.98,134.88 80.98,132.44 80.85,132.31
PWR_VDDQ on TOP: 114.3,40.59 113.97,40.92 113.97,41.91 114.18,42.11 119.21,42.11 119.26,42.17 119.26,42.57 119.38,42.7 119.74,42.7 119.78,42.66 119.78,41.84 119.55,41.61 119.33,41.61 119.13,41.4 119.13,40.87 118.85,40.59
PWR_VDDQ on BOTTOM: 110.39,38 110.24,38.15 110.24,40.18 110.37,40.31 112.4,40.31 113.67,41.58 119,41.58 119.26,41.33 119.26,40.83 120.77,39.32 120.77,38.57 120.65,38.44 119.28,38.44 118.83,38 ; 5 cut-outs
PWR_VDDQ_BOOTB on TOP: 119.82,31.8 119.82,31.35 119.76,31.29 119.48,31.29 119.28,31.09 118.75,31.09 118.65,31.19 118.19,31.19 118.06,31.32 118.06,31.6 118.16,31.7 118.72,31.7 118.88,31.85 119.76,31.85
PWR_VDDQ_PH on TOP: 113.85,33.63 113.64,33.83 113.64,34.14 114.2,34.7 114.2,35.89 114.56,36.25 115.14,36.25 115.45,35.94 115.45,34.09 114.99,33.63
PWR_VDDQ_PH on BOTTOM: 114.38,28.58 114.38,32.23 114.3,32.31 114.3,33.2 113.64,33.86 113.64,35.05 114.06,35.47 117.78,35.47 117.88,35.36 117.88,32.82 117.81,32.74 116.13,32.74 115.88,32.49 115.88,31.6 116.03,31.45 116.03,28.64 115.96,28.58
PWR_VDDQ_SNB on TOP: 112.84,33.73 111.99,34.58 111.99,35.89 112.13,36.03 113.67,36.03 113.73,35.96 113.73,34.49 113.52,34.28 113.52,33.89 113.36,33.73 ; 1 cut-out
PWR_VDDQ_VCC on TOP: 111.65,28.16 111.56,28.25 111.56,29.49 111.66,29.59 112.22,29.59 112.98,28.83 113.34,28.83 113.85,29.34 114.18,29.34 114.35,29.16 114.35,28.35 114.16,28.16 ; 1 cut-out
PWR_VDDQ_VDDQ on TOP: 119.41,40.89 119.29,41.01 119.29,41.35 119.43,41.49 119.57,41.49 120,41.92 120,42.71 120.12,42.83 121.22,42.83 121.38,42.68 121.38,42.38 119.88,40.89
PWR_VDDQ_VDDQ on TOP: 117.22,27.15 116.94,27.43 116.94,28.22 117,28.27 117.4,28.27 117.58,28.09 117.58,27.89 117.68,27.79 117.78,27.79 117.99,27.59 117.99,27.31 117.83,27.15
PWR_VDDQ_VLDOIN on TOP: 112.7,40.9 112.27,41.33 112.27,42.14 112.37,42.24 113.69,42.24 113.8,42.14 113.8,41.5 113.19,40.9
PWR_VDDQ_VLDOIN on TOP: 119.21,28.12 119.05,28.27 119.05,28.53 118.19,29.39 118.19,30.33 118.29,30.43 118.77,30.43 118.88,30.33 118.88,29.8 119.54,29.14 120.27,29.14 120.5,28.91 120.5,28.35 120.27,28.12 ; 1 cut-out
REGOUT on TOP: 47.76,84.83 47.74,84.84 47.74,86.15 48.14,86.54 49.15,86.54 49.53,86.16 49.53,85.58 49.41,85.45 49.02,85.45 48.4,84.83
REGOUT on BOTTOM: 48.36,85.17 48.21,85.32 48.21,85.95 48.09,86.08 48.09,86.56 48.14,86.62 49.1,86.62 49.53,86.18 49.53,85.6 49.36,85.42 49.08,85.42 48.82,85.17 ; 1 cut-out
RING2_HPMIC1 on TOP: 16.58,8.08 16.4,8.26 16.4,8.68 16.2,8.88 15.25,8.88 15.24,8.87 14.54,8.87 14.42,8.99 14.42,9.87 14.59,10.04 17.18,10.04 17.3,9.92 17.3,8.25 17.13,8.08
TP_VDD on TOP: 97.54,27.69 97.36,27.87 97.36,29.11 97.49,29.24 97.87,29.24 98.1,29.01 106.18,29.01 107.06,29.9 107.06,31.04 107.19,31.17 108.33,31.17 108.46,31.04 108.46,28.36 107.79,27.69 ; 4 cut-outs
TP_VDD on BOTTOM: 96.96,28.52 96.07,29.41 93.96,29.41 93.75,29.62 93.75,30.15 93.91,30.3 94.85,30.3 95.08,30.53 95.08,31.42 95.18,31.52 95.86,31.52 95.96,31.42 95.96,30.89 97.41,29.44 97.74,29.44 97.89,29.29 97.89,28.73 97.69,28.52
USB30_PS_VCC on TOP: 18.04,35.61 17.66,35.99 17.66,38.76 17.76,38.86 17.76,40.08 17.61,40.23 17.3,40.23 17.05,40.49 17.05,43.59 16.86,43.78 14.62,43.78 14.4,43.56 12.25,43.56 11.32,44.49 10.61,44.49 10.09,45.01 8.92,45.01 8.66,45.26 8.66,46.46 8.92,46.71 11.33,46.71 12.7,48.08 14.15,48.08 15.14,47.09 16.57,47.09 16.86,47.38 16.86,48.69 16.41,49.15 16.26,49.15 16.03,48.92 15.37,48.92 15.13,49.17 15.13,49.97 14.86,50.24 14.86,51.19 14.35,51.69 14.35,53.03 13.71,53.67 13.71,57.17 13.5,57.38 12.68,57.38 12.47,57.58 12.47,60.28 12.6,60.4 14.35,60.4 14.75,60.01 14.75,59.01 15.89,57.86 17.33,57.86 17.61,57.58 17.61,56.71 17.58,56.68 15.73,56.68 15.5,56.45 15.5,53.82 19.15,50.17 19.15,48.26 19.87,47.55 19.87,46.23 20.07,46.03 20.42,46.03 20.58,46.18 20.58,48.49 21.77,49.68 21.77,50.57 21.85,50.65 23.07,50.65 23.22,50.5 23.22,48.03 22.48,47.3 22.48,45.21 21.75,44.48 21.75,42.5 19.33,40.08 19.33,36.15 18.8,35.61 ; 2 cut-outs
USB30_PS_VCC on BOTTOM: 16.08,56.64 14.3,58.42 12.86,58.42 12.45,58.83 12.45,60 12.98,60.53 14.38,60.53 16.21,58.7 18.98,58.7 19.33,58.35 19.33,56.71 19.26,56.64 ; 4 cut-outs
USB_ADT on TOP: 36.55,121.21 36.3,121.46 36.3,122.18 35.94,122.53 35.94,125.91 36.07,126.04 38.48,126.04 38.74,125.78 38.74,125.34 39.04,125.04 39.04,124.84 38.74,124.54 38.74,124 38.99,123.75 39.22,123.75 39.35,123.62 39.35,122 39.2,121.85 38.94,121.85 38.66,121.57 38.2,121.57 37.85,121.21 ; 1 cut-out
V_SM_VREF_CNTA on TOP: 70.72,40.36 70.59,40.49 70.59,40.92 70.64,40.97 72.67,40.97 72.98,41.28 72.98,41.78 73.1,41.91 73.64,41.91 73.71,41.84 73.71,40.84 73.23,40.36
VCP_VBUS on TOP: 42.55,123.37 42.42,123.5 42.42,123.65 42.21,123.86 42.15,123.86 42.14,123.88 42.04,123.88 41.94,123.98 41.94,124.33 41.79,124.49 41.79,126.54 41.91,126.67 43.31,126.67 43.44,126.54 43.44,124.64 43.31,124.51 43.06,124.51 42.83,124.28 42.83,123.47 42.73,123.37
VREG3PD on TOP: 51.34,127.89 51.23,127.99 51.23,128.47 51.26,128.5 51.83,128.5 52.64,129.3 53.23,129.3 53.55,128.99 54.75,128.99 54.93,128.81 54.93,127.99 54.83,127.89 ; 3 cut-outs

Small or netless copper shapes (teardrops, artwork), in the pictures only: 53 on L2SGND, 53 on L3, 53 on L4, 53 on L5SGND, 2 on TOP, 2 on BOTTOM

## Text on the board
Ref Des/Silkscreen Bottom: 15 Narrow | 14L | 14L/Bolt15 | 15L/2SP/BT | 14L/15L | 2SP/15 Narrow | F6501:1.1A/6V | X1801:24MHZ | F5503:1.1A/24V
User.Comments: CR_2_2 | CR_UNNAMED_1 | SIR_MAKOY_1107 | CR_TEST_1
Ref Des/Silkscreen Top: 17938-1 | FW8G6 | MADE IN TAIWAN | Bolt-L UMA MB | X1802:32.768KHZ | X3101:25MHZ | F5701:1.1A/6V | X2401:32.768KHZ | F5504:1.1A/6V | F5505:1.1A/6V | F5506:1.1A/6V
User.33: ByImpedance:100.0_DP@_REF_L1=("5.0/11.0(L2)" "4.0/7.0(L2)" "3.5/5.0(L2)")|_REF_L6=("4.0/7.0(L5)" "3.5/5.0(L5)" "5.0/11.0(L5)")|Type="DP"|_REF_L4=("4.0/9.0(L2/L5)" "3.5/7.0(L2/L5)")|_REF_L3=("4.0/9.0(L2/L5)" "3.5/7.0(L2/L5)")|imp="100.0" | ByImpedance:110.0_DP@_REF_L1=("3.5/8.0(L2)" "4.0/12.0(L2)")|_REF_L6=("4.0/12.0(L5)" "3.5/8.0(L5)")|Type="DP"|imp="110.0" | ByImpedance:33.0_SE@_REF_L2=("6.5(L1/L3)")|_REF_L1=("12.0(L2)")|_REF_L6=("12.0(L5)")|Type="SE"|_REF_L4=("11.5(L2/L5)")|_REF_L3=("11.5(L2/L5)")|imp="33.0" | ByImpedance:35.0_SE@_REF_L2=("6.0(L1/L3)")|_REF_L1=("11.0(L2)")|_REF_L6=("11.0(L5)")|Type="SE"|_REF_L4=("10.5(L2/L5)")|_REF_L3=("10.5(L2/L5)")|imp="35.0" | ByImpedance:37.5_SE@_REF_L2=("5.0(L1/L3)")|_REF_L1=("10.0(L2)")|_REF_L6=("10.0(L5)")|Type="SE"|_REF_L4=("9.0(L2/L5)")|_REF_L3=("9.0(L2/L5)")|imp="37.5" | ByImpedance:40.0_SE@_REF_L2=("4.5(L1/L3)")|_REF_L1=("8.5(L2)")|_REF_L6=("8.5(L5)")|Type="SE"|_REF_L4=("8.0(L2/L5)" "8.0(L3/L5)")|_REF_L3=("8.0(L2/L5)")|imp="40.0" | ByImpedance:42.0_SE@_REF_L2=("4.0(L1/L3)")|_REF_L1=("8.0(L2)")|_REF_L6=("8.0(L5)")|Type="SE"|_REF_L4=("7.5(L2/L5)")|_REF_L3=("7.5(L2/L5)")|imp="42.0" | ByImpedance:43.0_SE@_REF_L2=("3.9(L1/L3)")|_REF_L1=("7.5(L2)")|_REF_L6=("7.5(L5)")|Type="SE"|_REF_L4=("7.0(L2/L5)")|_REF_L3=("7.0(L2/L5)")|imp="43.0" | ByImpedance:45.0_SE@_REF_L2=("3.5(L1/L3)")|_REF_L1=("7.0(L2)")|_REF_L6=("7.0(L5)")|Type="SE"|_REF_L4=("6.5(L2/L5)" "6.5(L3/L5)")|_REF_L3=("6.5(L2/L5)")|imp="45.0" | ByImpedance:48.0_SE@_REF_L1=("6.0(L2)")|_REF_L6=("6.0(L5)")|Type="SE"|_REF_L4=("5.5(L2/L5)")|_REF_L3=("5.5(L2/L5)")|imp="48.0" | ByImpedance:50.0_SE@_REF_L1=("15.0/15.0/15.0(L1/L3)" "5.5(L2)" "7.0/13.0/7.0(L1/L3)")|_REF_L6=("5.5(L5)" "15.0/15.0/15.0(L3/L6)" "7.0/13.0/7.0(L4/L6)")|Type="SE"|_REF_L4=("5.0(L3/L5)" "5.0(L2/L5)")|_REF_L3=("5.0(L2/L4)" "5.0(L2/L5)")|imp="50.0" | ByImpedance:52.0_SE@_REF_L1=("5.0(L2)")|_REF_L6=("5.0(L5)")|Type="SE"|_REF_L4=("4.5(L2/L5)")|_REF_L3=("4.5(L2/L5)")|imp="52.0" | ByImpedance:55.0_SE@_REF_L1=("4.5(L2)")|_REF_L6=("4.5(L5)")|Type="SE"|_REF_L4=("4.0(L2/L5)")|_REF_L3=("4.0(L2/L5)")|imp="55.0" | ByImpedance:60.0_SE@_REF_L1=("3.5(L2)")|_REF_L6=("3.5(L5)")|Type="SE"|imp="60.0" | ByImpedance:65.0_DP@_REF_L2=("6.0/5.0(L1/L3)")|_REF_L1=("10.0/5.0(L2)")|_REF_L6=("10.0/5.0(L5)")|Type="DP"|_REF_L4=("9.0/5.0(L2/L5)")|_REF_L3=("9.0/5.0(L2/L5)")|imp="65.0" | ByImpedance:68.0_DP@_REF_L2=("5.5/5.0(L1/L3)")|_REF_L1=("9.0/5.0(L2)")|_REF_L6=("9.0/5.0(L5)")|Type="DP"|_REF_L4=("8.0/5.0(L2/L5)")|_REF_L3=("8.0/5.0(L2/L5)")|imp="68.0" | ByImpedance:70.0_DP@_REF_L2=("5.0/4.0(L1/L3)")|_REF_L1=("8.5/5.0(L2)")|_REF_L6=("8.5/5.0(L5)")|Type="DP"|_REF_L4=("6.5/3.5(L3/L5)" "8.0/6.0(L2/L5)" "7.5/5.0(L2/L5)" "6.5/3.5(L2/L5)")|_REF_L3=("8.0/6.0(L2/L5)" "7.5/5.0(L2/L5)" "6.5/3.5(L2/L5)")|imp="70.0" | ByImpedance:72.0_DP@_REF_L2=("5.0/5.0(L1/L3)")|_REF_L1=("7.5/4.5(L2)")|_REF_L6=("7.5/4.5(L5)")|Type="DP"|_REF_L4=("6.0/3.5(L2/L5)" "6.5/4.0(L2/L5)")|_REF_L3=("6.0/3.5(L2/L5)" "6.5/4.0(L2/L5)")|imp="72.0" | ByImpedance:75.0_DP@_REF_L2=("4.5/5.0(L1/L3)")|_REF_L1=("7.0/4.0(L2)")|_REF_L6=("7.0/4.0(L5)")|Type="DP"|_REF_L4=("5.5/3.5(L3/L5)" "7.0/6.0(L3/L5)" "5.5/3.5(L2/L5)" "7.0/6.0(L2/L5)")|_REF_L3=("5.5/3.5(L2/L5)" "7.0/6.0(L2/L5)")|imp="75.0" | ByImpedance:80.0_DP@_REF_L2=("3.5/4.0(L1/L3)")|_REF_L1=("6.0/4.5(L2)")|_REF_L6=("6.0/4.5(L5)")|Type="DP"|_REF_L4=("6.0/6.0(L2/L5)" "4.5/3.5(L3/L5)" "6.0/6.0(L3/L5)" "4.5/3.5(L2/L5)")|_REF_L3=("6.0/6.0(L2/L5)" "4.5/3.5(L2/L5)")|imp="80.0" | ByImpedance:83.0_DP@_REF_L2=("3.5/4.5(L1/L3)")|_REF_L1=("5.0/4.0(L2)")|_REF_L6=("5.0/4.0(L5)")|Type="DP"|_REF_L4=("4.5/4.0(L2/L5)")|_REF_L3=("4.5/4.0(L2/L5)")|imp="83.0" | ByImpedance:85.0_DP@_REF_L2=("3.5/5.5(L1/L3)")|_REF_L1=("6.0/6.0(L2)" "5.5/5.0(L2)" "5.0/4.5(L2)")|_REF_L6=("6.0/6.0(L5)" "5.5/5.0(L5)" "5.0/4.5(L5)")|Type="DP"|_REF_L4=("5.0/5.5(L2/L5)" "4.5/4.5(L2/L5)" "4.0/4.0(L3/L5)")|_REF_L3=("5.0/5.5(L2/L5)" "4.5/4.5(L2/L5)")|imp="85.0" | ByImpedance:88.0_DP@_REF_L2=("3.5/7.5(L1/L3)")|_REF_L1=("5.0/5.0(L2)")|_REF_L6=("5.0/5.0(L5)")|Type="DP"|_REF_L4=("4.0/4.5(L2/L5)")|_REF_L3=("4.0/4.5(L2/L5)")|imp="88.0" | ByImpedance:90.0_DP@_REF_L1=("4.0/4.0(L2)" "5.0/6.0(L2)")|_REF_L6=("5.0/6.0(L5)" "4.0/4.0(L5)")|Type="DP"|_REF_L4=("4.0/5.0(L3/L5)" "5.0/8.0(L2/L5)" "4.0/5.0(L2/L5)" "5.0/8.0(L3/L5)")|_REF_L3=("5.0/8.0(L2/L5)" "4.0/5.0(L2/L5)" "4.0/5.0(L2/L4)" "5.0/8.0(L2/L4)")|imp="90.0" | ByImpedance:95.0_DP@_REF_L1=("4.0/5.0(L2)" "3.5/4.0(L2)")|_REF_L6=("4.0/5.0(L5)" "3.5/4.0(L5)")|Type="DP"|_REF_L4=("4.0/6.5(L2/L5)" "3.5/5.0(L2/L5)")|_REF_L3=("4.0/6.5(L2/L5)" "3.5/5.0(L2/L5)")|imp="95.0" | LayerIndex:nil | Source:6-1.0-1u.xls | artWorks:("_REF_L3" "_REF_L4" "_REF_L6" "_REF_L1" "_REF_L2") | gtImpOutlineUsed:BOARD GEOMETRY/PANEL_OUTLINE
User.34: Board Accuracy Check,Nov 05 15:59:50 2018,Passed | Dummy-Static-No Shape On Layer Check,Nov 05 15:59:51 2018,212 errors | Split Plane Check,Nov 05 15:59:50 2018,212 errors
User.40: This gerber is just for your reference to find the DP impedance traces in layer L1. | DP IMPEDANCE TABLE: L1 | * - Denotes that this Impedance | is NOT used | IMP(Ohm) | *65.0 | *68.0 | *70.0 | *72.0 | *75.0 | *80.0 | *83.0 | *85.0 | 85.0 | *88.0 | *90.0 | *95.0 | *100.0 | 100.0 | *110.0 | WIDTH(mils) | 10.0/5.0 | 9.0/5.0 | 8.5/5.0 | 7.5/4.5 | 7.0/4.0 | 6.0/4.5 | 5.0/4.0 | 6.0/6.0 | 5.5/5.0 | 5.0/4.5 | 5.0/5.0 | 4.0/4.0 | 5.0/6.0 | 4.0/5.0 | 3.5/4.0 | 5.0/11.0 | 4.0/7.0 | 3.5/5.0 | 3.5/8.0 | 4.0/12.0 | TYPE | DP | Ref. Plane | L2
User.42: This gerber is just for your reference to find the SE impedance traces in layer L1. | SE IMPEDANCE TABLE: L1 | * - Denotes that this Impedance | is NOT used | IMP(Ohm) | *33.0 | *35.0 | *37.5 | 40.0 | *42.0 | *43.0 | *45.0 | *48.0 | 50.0 | *52.0 | *55.0 | *60.0 | WIDTH(mils) | 12.0 | 11.0 | 10.0 | 8.5 | 8.0 | 7.5 | 7.0 | 6.0 | 5.5 | 5.0 | 4.5 | 3.5 | TYPE | SE | Ref. Plane | L2
